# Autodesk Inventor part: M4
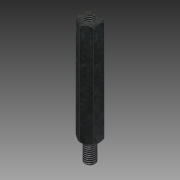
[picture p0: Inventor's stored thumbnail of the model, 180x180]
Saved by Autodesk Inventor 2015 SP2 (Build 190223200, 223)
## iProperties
Created: 2012-08
Part Number: M4
Material: Stahl
Document SubType Name: Modeling
Designer: rYan
Density: 7.85 g/cm^3
Mass: 1.74537 g
Surface Area: 3.04272 cm^2
Volume: 0.22234 cm^3
Appearance: Platte
Author: rYan
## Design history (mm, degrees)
derived "Abstandsbolzen Typ B.ipt"
feature "Volumenkörper1::Abstandsbolzen Typ B.ipt"
tag "Bezeichnung1"
node "Volumenkörper1"
other parameters: "SW" = 7, "d2" = 0, "l_" = 9, "d9" = 118 deg, "GA_" = 4, "A_" = 8, "d13" = 0, "d17" = 0.25, "d20" = 45 deg
